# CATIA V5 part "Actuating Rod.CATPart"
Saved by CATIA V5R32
Part number: Actuating Rod
Bounding box of the stored display mesh (mm): x -17.5 to 17.5, y -11.818 to 195.322, z -21 to 21
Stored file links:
  D:\PROJECTS\Project 2022\CATIA V5 6R 2022\Resources\Part Files\c12_catia_v5_6r2022_prt\c12_catia_v5-6r2022 figr_12-26\Actuating Rod.CATPart
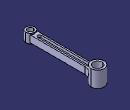
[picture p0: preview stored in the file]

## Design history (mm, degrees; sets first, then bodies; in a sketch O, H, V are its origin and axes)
Body1 (main body)
  Sketch1 on xy-plane, origin (0, 0, 0), H (1, 0, 0), V (0, 1, 0)
    arc A1 centre (0, 0) radius 12 from (-9, 7.9373) to (9, 7.9373) ccw
    arc A2 centre (0, 178) radius 17.5 from (13.5991, 166.9857) to (-13.5991, 166.9857) ccw
    point P1 (0, 178)
    line L1 (9, 154) -> (9, 7.9373)
    point P2 (9, 154)
    point P3 (9, 7.9373)
    arc A3 centre (29.6324, 154) radius 20.6324 from (9, 154) to (13.5991, 166.9857) cw
    point P5 (13.5991, 166.9857)
    point P6 (-13.5991, 166.9857)
    point P7 (-9, 154)
    arc A4 centre (-29.6324, 154) radius 20.6324 from (-9, 154) to (-13.5991, 166.9857) ccw
    point P9 (-9, 7.9373)
    line L2 (-9, 154) -> (-9, 7.9373)
    radius A2 = 17.5
    radius A1 = 12
    distance O P1 = 178
    distance V L1 = 9
    distance P1 P2 V = 24
    coincidence: P1 V
    vertical: L1 V
    tangency: A3 L1, A3 A2
    symmetry: P5 P6 V, P2 P7 V, A3 A4 V, P3 P9 V, L1 L2 V
  Pad1: profile Sketch1, direction (0, 0, 1), length 9, mirrored extent
  Sketch2 on xy-plane, origin (0, 0, 0), H (1, 0, 0), V (0, 1, 0)
    circle A1 centre (0, 0) radius 12
    reference projected arc E1 centre (0, 0) radius 12 from (-9, 7.9373) to (9, 7.9373) ccw from edge of Pad1
    reference projected arc E2 centre (0, 0) radius 12 from (-9, 7.9373) to (9, 7.9373) ccw from edge of Pad1
    reference projected arc E3 centre (0, 0) radius 12 from (-9, 7.9373) to (9, 7.9373) ccw from edge of Pad1
    concentricity: A1 E1, A1 E2
    tangency: A1 E3
  Pad2: profile Sketch2, direction (0, 0, 1), length 12, mirrored extent
  Sketch3 on xy-plane, origin (0, 0, 0), H (1, 0, 0), V (0, 1, 0)
    circle A1 centre (0, 178) radius 17.5
    point P1 (0, 178)
    reference projected arc E1 centre (0, 178) radius 17.5 from (13.5991, 166.9857) to (-13.5991, 166.9857) ccw from edge of Pad1
    reference projected arc E2 centre (0, 178) radius 17.5 from (13.5991, 166.9857) to (-13.5991, 166.9857) ccw from edge of Pad1
    coincidence: P1 V
    concentricity: A1 E1
    tangency: E2 A1
  Pad3: profile Sketch3, direction (0, 0, 1), length 21, mirrored extent
  Sketch4 on xy-plane, origin (0, 0, 0), H (1, 0, 0), V (0, 1, 0)
    circle A1 centre (0, 178) radius 12
    point P1 (0, 178)
    circle A2 centre (0, 0) radius 7.5
    reference projected circle E1 centre (0, 178) radius 17.5 from edge of Pad3
    radius A1 = 12
    radius A2 = 7.5
    coincidence: P1 V
    concentricity: A1 E1
  Pocket1: profile Sketch4, direction (0, 0, -1), length 21, mirrored extent
  Sketch5 on xy-plane, origin (0, 0, 0), H (1, 0, 0), V (0, 1, 0)
    construction line L1 (0, 24) -> (0, 154)
    point P1 (0, 24)
    line L2 (-5, 24) -> (-5, 154)
    line L3 (5, 154) -> (5, 24)
    arc A1 centre (0, 154) radius 5 from (-5, 154) to (5, 154) cw
    arc A2 centre (0, 24) radius 5 from (5, 24) to (-5, 24) cw
    length L1 = 130
    distance H P1 = 24
    radius A1 = 5
    coincidence: P1 V
    vertical: L1 V
    tangency: A1 L2, A2 L2, A1 L3, A2 L3
    parallelism: L1 L2
  Pocket2: profile Sketch5, direction (0, 0, -1), through (limit type 6), opposite side length -2.5
  Mirror1: of Pocket2, Sketch5, about xy-plane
